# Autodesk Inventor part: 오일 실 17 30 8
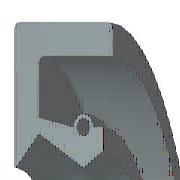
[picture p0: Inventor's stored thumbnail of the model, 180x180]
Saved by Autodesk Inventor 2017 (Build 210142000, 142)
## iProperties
Created: 2012-02
Part Number: 오일 실 17 30 8
Material: 고무
Description: 오일-실
Document SubType Name: Modeling
Standard: KS B 2804
Designer: mduedu
Standards Organization: KS
Language: ko-KR
Size Designation: D - 17 30 8
Categories: <MemberInstance><Categories><Category DisplayName="샤프트 부품" InternalName="7f7aeb1f-a693-4053-b835-cee3144e0d98" Mnemonic="SHFT"><Category DisplayName="실링" Intern
Density: 0.93 g/cm^3
Appearance: 고무 - 검은색 - 버전 1.1
Mass: 2.05499 g
Surface Area: 29.2219 cm^2
Volume: 2.20967 cm^3
IsCustomPart: 1
Author: mduedu
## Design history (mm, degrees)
revolve "본체" stored, may be unused: angle "d17" = 90 deg
revolve "스프링1" stored, may be unused: angle "d18" = 90 deg
fillet "모깎기3" dims "d43" = 0.5
body "Solid1"
sketch "스케치1"
  geometry: L1 (0, 15)-(8, 15); L2 (8, 13.25)-(1.75, 13.25); L3 (1.75, 10.25)-(4.9, 8.5); L4 (4.9, 8.5)-(0, 8.5); L5 (0, 0)-(9.586, 0) reference; L6 (4.9, 8.5)-(6.3, 9.375); L7 (0, 18)-(0, -3) reference; L8 (-1.941, 0)-(11.507, 0) reference; L9 (4.2, 10.6)-(1.75, 11.21); L10 (1.75, 11.21)-(1.75, 13.25); L11 (0, 15)-(0, 8.588); L12 (4.9, 8.5)-(0, 8.5); L13 (1.75, 10.25)-(0.152, 8.528); L14 (8, 15)-(8, 13.25); L15 (5.6, 10.6)-(6.3, 10.6); L16 (6.3, 10.6)-(6.3, 9.375); C1 r 0.455 at (4.9, 10.6); A1 r 0.7 centre (4.9, 10.6) between (5.6, 10.6) and (4.2, 10.6); A2 r 0.088 centre (0.088, 8.588) between (0, 8.588) and (0.152, 8.528); 1 further point
  constraints: 28 end point, 5 horizontal alignment, 5 point on line, 4 point on circle, 4 vertical alignment, 3 centre point, 3 tangent, 2 collinear, 2 horizontal, 2 perpendicular, 1 coincident, 1 parallel
  dimensions: "d0" = 30 diameter of L1 L5 (= SD2); "d1" = 1.75 distance of L1.end L2.start (= SD); "d2" = 0.91 diameter of C1 (= SPDI); "d3" = 1.4 diameter of A1 (= SPDA); "d4" = 17 diameter of L3.end L5 (= NND); "d5" = 20.5 diameter of L3.start L5 (= TKDM); "d7" = 22.42 diameter of L9.end L5 (= TKDM + 0.24 x SWDT); "d8" = 1.75 distance between parallel lines of L11 L10 (= SD); "d9" = 4.9 distance from line of L11 C1.centre (= SPDST); "d10" = 21.2 diameter of C1.centre L5 (= HLDM); "d11" = 0.0875 radius of A2 (= 0.25 x LAB); "d12" = 6.3 distance between parallel lines of L11 L16 (= SDI); "d13" = 18.75 diameter of L6.end L5 (= ABDM); "d14" = 8 distance from line of L11 L1.end (= SWDT)
fillet "모깎기1" dims "d6" = 0.3 (= RR)
other parameters: "SD2" = 30 [user parameter; used in 1 equation term], "SWDT" = 8 [user parameter; used in 2 equation terms], "RR" = 0.3 [user parameter; used in 1 equation term], "SD" = 1.75 [user parameter; used in 2 equation terms], "NND" = 17 [user parameter; used in 1 equation term], "SPDA" = 1.4 [user parameter; used in 1 equation term], "SPDI" = 0.91 [user parameter; used in 1 equation term], "TKDM" = 20.5 [user parameter; used in 2 equation terms], "HLDM" = 21.2 [user parameter; used in 1 equation term], "ABDM" = 18.75 [user parameter; used in 1 equation term], "SDI" = 6.3 [user parameter; used in 1 equation term], "SPDST" = 4.9 [user parameter; used in 1 equation term], "LAB" = 0.35 [user parameter; used in 1 equation term], "d15" = 0, "d16" = 0, "d19" = 0
